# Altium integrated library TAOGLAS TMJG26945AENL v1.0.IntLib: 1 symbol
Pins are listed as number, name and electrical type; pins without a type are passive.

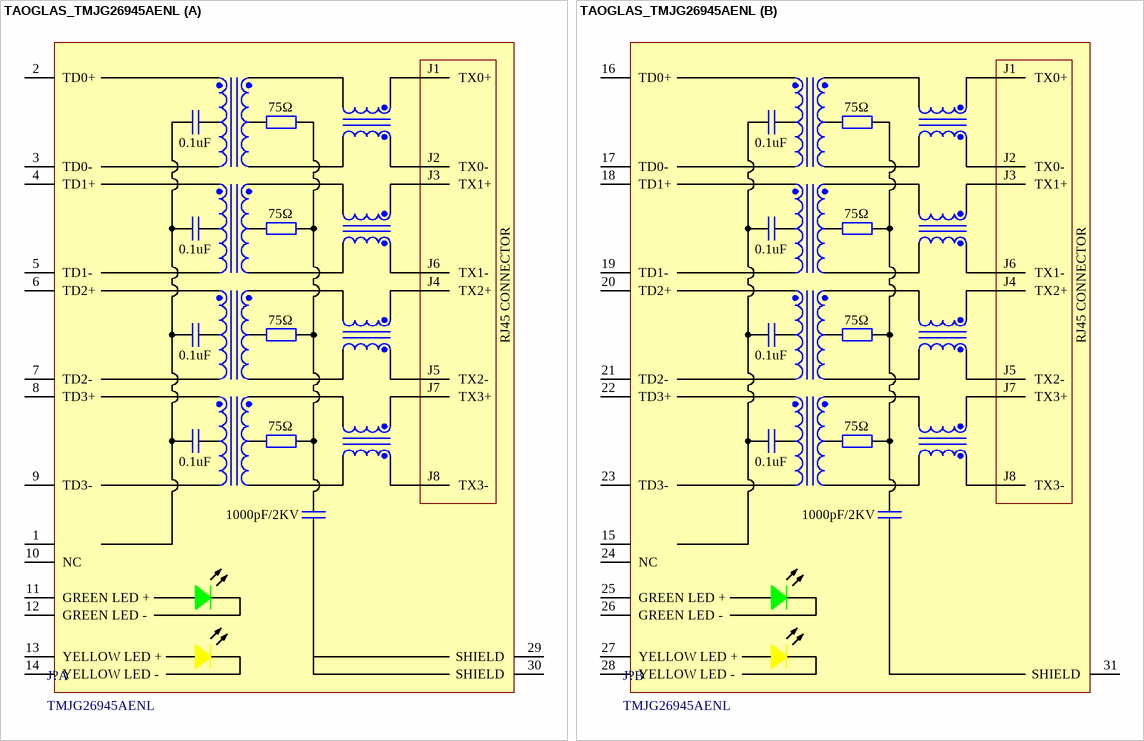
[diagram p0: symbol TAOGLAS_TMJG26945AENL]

## TAOGLAS_TMJG26945AENL
designator J?, comment TMJG26945AENL
RJ45 connector with integrated magnetics 1G Base-T Dual Ports Tab-DOWN with right angle THT mount and LEDs; ComponentLibStatus: Created; MFG: Taoglas; Temp_High: +85C; Temp_Low: -40C
footprint TAOGLAS_TMJG26945AENL (RJ45 connector with integrated magnetics 1G Base-T Dual Ports Tab-DOWN with right angle THT mount and LEDs)
part A pins: 1, 2 TD0+, 3 TD0-, 4 TD1+, 5 TD1-, 6 TD2+, 7 TD2-, 8 TD3+, 9 TD3-, 10 NC, 11 GREEN LED +, 12 GREEN LED -, 13 YELLOW LED +, 14 YELLOW LED -, 29 SHIELD, 30 SHIELD
part B pins: 15, 16 TD0+, 17 TD0-, 18 TD1+, 19 TD1-, 20 TD2+, 21 TD2-, 22 TD3+, 23 TD3-, 24 NC, 25 GREEN LED +, 26 GREEN LED -, 27 YELLOW LED +, 28 YELLOW LED -, 31 SHIELD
